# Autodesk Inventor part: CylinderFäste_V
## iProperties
Created: 2007-05
Part Number: CylinderFäste_V
Document SubType Name: Modeling
Designer: kurs1
Density: 1 g/cm^3
Author: kurs1
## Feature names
1. Derived Body1 [Tagging]
